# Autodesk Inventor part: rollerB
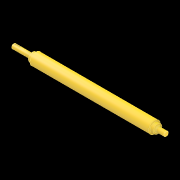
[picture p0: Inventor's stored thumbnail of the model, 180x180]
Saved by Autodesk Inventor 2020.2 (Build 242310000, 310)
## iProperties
Manager: PART
Category: 13
Company: 14
Created: 2020-10
Part Number: rollerB
Material: Generic
Document SubType Name: Modeling
Designer: Apardo
Density: 1 g/cm^3
Appearance: Glossy - Gold
Project: PLATE ROLLING MACHINE
Cost Center: 1
Description: ROLLER B
Engineer: STEEL C45
Vendor: 13
Stock Number: 1.10
Engr Approved By: D. JAEGER
Author: Apardo
Revision Number: 1.0
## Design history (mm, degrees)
sketch "Sketch1"
  geometry: L1 (0, 0)-(-263.363, 0); L2 (-193, 0)-(-193, 6); L3 (-137, 11)-(-137, 15); L4 (-137, 15)-(163, 15); L5 (163, 15)-(163, 11); L6 (163, 11)-(171, 11); L7 (171, 11)-(171, 7.5); L8 (171, 7.5)-(173, 7.5); L9 (193, 6)-(193, 0); L10 (193, 0)-(-193, 0); L11 (173, 7.5)-(173, 6); L12 (173, 6)-(193, 6); L13 (-193, 6)-(-147, 6); L14 (-147, 6)-(-147, 7.5); L15 (-147, 7.5)-(-145, 7.5); L16 (-145, 7.5)-(-145, 11); L17 (-145, 11)-(-137, 11); 1 further point
  constraints: 34 end point, 12 perpendicular, 2 horizontal, 2 vertical, 1 point on line
  dimensions: "d0" = 386 distance of L9.end L2.start; "d1" = 193 distance from line of L1.start L2 (= 0.5 x d0); "d2" = 30 diameter of L4 L1; "d3" = 15 diameter of L8 L1; "d4" = 22 diameter of L6 L1; "d6" = 30 distance from line of L5 L9.end; "d11" = 12 diameter of L12 L1; "d12" = 20 distance of L9.start L11.end; "d13" = 22 distance between parallel lines of L7 L9; "d14" = 12 diameter of L13 L1; "d15" = 15 diameter of L15 L1; "d16" = 22 diameter of L17 L1; "d17" = 56 distance between parallel lines of L3 L2; "d18" = 48 distance between parallel lines of L2 L16; "d19" = 46 distance of L2.end L13.end
revolve "Revolution1" sketch "Sketch1" stored, may be unused: angle "d7" = 90 deg
chamfer "Chamfer1" distance "d8" = 1; stored, may be unused: second distance "d9" = 2, angle "d10" = 45 deg
workplane "Work Plane1"
sketch "Sketch2"
  geometry: L1 (190, 0)-(175, 0); L2 (188, 2)-(177, 2); L3 (177, -2)-(188, -2); L4 (193, 6)-(193, -6) reference; A1 r 2 centre (188, 0) between (188, -2) and (188, 2); A2 r 2 centre (177, 0) between (177, 2) and (177, -2); 4 further points
  constraints: 8 end point, 7 point on circle, 4 tangent, 2 centre point, 2 midpoint, 2 point on line, 1 horizontal, 1 horizontal alignment, 1 parallel
  dimensions: "d21" = 3 distance from line of L4 L1.start; "d22" = 15 distance of L1.start L1.end; "d23" = 2 radius of A2
extrude "Extrusion1" cut sketch "Sketch2" distance "d24" = 4.503; taper "d25" = 0 deg
body "Solid1"
other parameters: "d20" = 8
